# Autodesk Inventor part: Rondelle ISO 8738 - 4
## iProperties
Created: 2011-01
Part Number: Rondelle ISO 8738 - 4
Document SubType Name: Modeling
Designer: eric
Density: 1 g/cm^3
Mass: 0.0301593 g
Surface Area: 1.05558 cm^2
Volume: 0.0301593 cm^3
Author: eric
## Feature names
1. Base1
